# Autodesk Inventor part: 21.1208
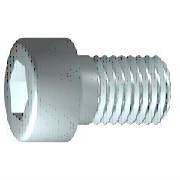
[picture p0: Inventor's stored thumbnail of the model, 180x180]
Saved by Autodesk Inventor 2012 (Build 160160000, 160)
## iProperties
Created: 2006-02
Part Number: 21.1208
Material: Steel, Mild
Description: M8 x 35 SHCS
Document SubType Name: Modeling
Standard: DIN 7984
Designer: Andy Moles
Standards Organization: DIN
Language: en-US
Size Designation: M8 x 35
Categories: <MemberInstance><Categories><Category DisplayName="Fasteners" InternalName="e4da775c-781d-43d5-af7c-5136215cf5a6" Mnemonic="FSTN"><Category DisplayName="Bolts"
Density: 7.86 g/cm^3
Mass: 18.1893 g
Surface Area: 13.9466 cm^2
Volume: 2.31416 cm^3
Vendor: S
Author: Andy Moles
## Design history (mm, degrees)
revolve "Body" stored, may be unused: angle "d10" = 90 deg
sketch "Sketch2"
  geometry: L1 (0, -9.1)-(0, 9.1) reference; L2 (-9.1, 0)-(9.1, 0) reference; L3 (2.887, 0)-(1.443, -2.5); L4 (1.443, -2.5)-(-1.443, -2.5); L5 (-1.443, -2.5)-(-2.887, 0); L6 (-2.887, 0)-(-1.443, 2.5); L7 (-1.443, 2.5)-(1.443, 2.5); L8 (1.443, 2.5)-(2.887, 0); 2 further points
  constraints: 12 end point, 1 coincident, 1 horizontal alignment, 1 point on line, 12 other
extrude "Slot" join sketch "Sketch2" stored distance "d11" = 10; taper "d12" = 0 deg
body "Solid1"
workplane "Work Plane1"
fillet "Fillet1" dims "d17" = 0.8 (= RR)
feature "Thread" dims "d13" = 22 (= GEL), "d14" = 0
chamfer "Chamfer1" distance "d15" = 0.76681 (= -0.5 x SPD + 0.5 x GD); stored, may be unused: second distance "d16" = 0.76681 (= GUL), angle "d27" = 45 deg
sketch "Sketch1"
  geometry: L1 (0.467, 0)-(35, 0); L2 (35, 0)-(35, 4); L3 (35, 4)-(13, 4); L4 (13, 4)-(12.233, 4); L5 (12.233, 4)-(0, 4); L6 (0, 4)-(0, 6.5); L7 (0, 6.5)-(-5, 6.5); L8 (-5, 6.5)-(-5, 2.887); L9 (-5, 2.887)-(-1.2, 2.887); L10 (-1.2, 2.887)-(0.467, 0); L11 (-13, 0)-(43, 0) reference; L12 (0, -1.3)-(0, 7.8) reference; L13 (13, 4)-(0, 4)
  constraints: 22 end point, 6 parallel, 2 collinear, 2 perpendicular, 1 horizontal, 1 point on line
  dimensions: "d1" = 22 distance from line of L3.end L2 (= GEL); "d2" = 0.76691 distance of L4.end L3.end (computed from GAL); "d3" = 5 distance between parallel lines of L8 L6 (= KOH); "d4" = 3.8 distance of L8.end L9.end (= INTI); "d5" = 60 deg angle of L10 L1; "d6" = 8 diameter of L3 L1 (= GD); "d7" = 8 diameter of L5 L1 (= BDM); "d8" = 5.7735 diameter of L9 L1 (= 1.1547 x SW); "d9" = 13 diameter of L7 L1 (= KOD); "d26" = 35 distance between parallel lines of L12 L2 (= NLG)
other parameters: "GD" = 8 (= NND) [user parameter; used in 2 equation terms], "NLG" = 35 [user parameter; used in 1 equation term], "GEL" = 22 [user parameter; used in 2 equation terms], "KOD" = 13 [user parameter; used in 1 equation term], "KOH" = 5 [user parameter; used in 1 equation term], "INTI" = 3.8 [user parameter; used in 1 equation term], "GAL" = 0.76681 (= 0.61345 x PTC) [user parameter; used in 1 equation term], "GUL" = 0.76681 (= 0.61345 x PTC) [user parameter; used in 1 equation term], "BDM" = 8 (= NND) [user parameter; used in 1 equation term], "SW" = 5 [user parameter; used in 2 equation terms], "RR" = 0.8 [user parameter; used in 1 equation term], "SPD" = 6.46637 (= NND - 1.2269 x PTC) [user parameter; used in 1 equation term], "d19" = 0, "d28" = 0, "d29" = 0, "TOA" = 30 deg [user parameter], "GD1" = 6.46637 (= THREADDIA - 1.2269 x PTC) [user parameter], "THREADDIA" = 8 [user parameter; used in 1 equation term], "FAWI" = 45 deg [user parameter], "ANG" = 120 deg [user parameter], "TPU" = 8 (computed from PTC) [user parameter], "PTC" = 1.25 [user parameter; used in 5 equation terms], "NND" = 8 [user parameter; used in 3 equation terms], "E0" = 5.775 (= 1.155 x SW) [user parameter]
